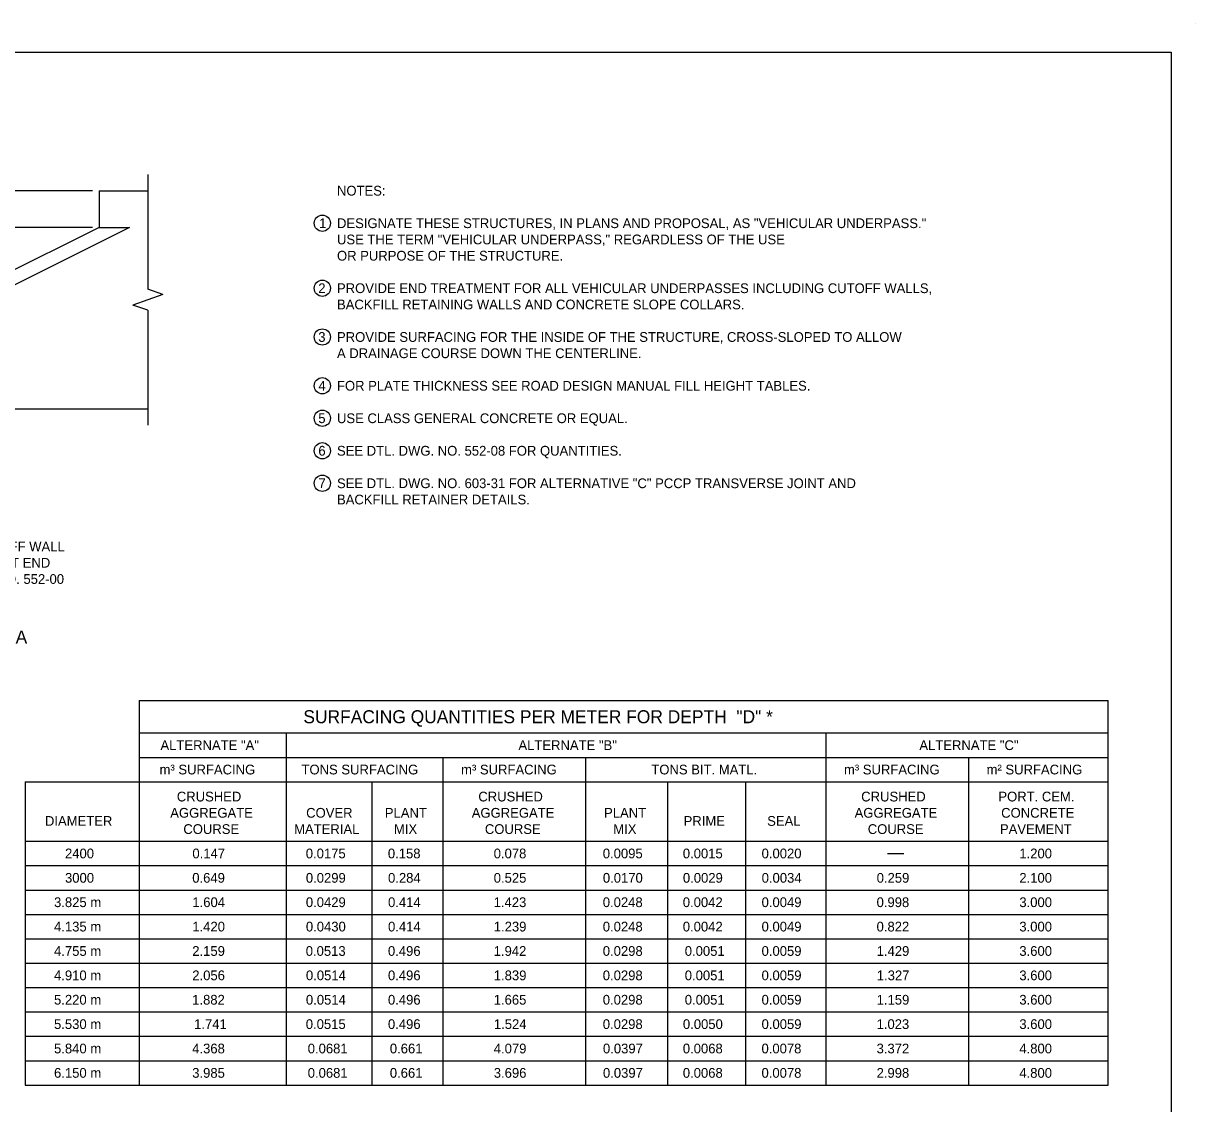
# Model space of a CAD drawing. Extents: x 49991.4 to 50021, y 49987.6 to 50011.4.
# Drawn here: x 50009.69 to 50016.9, y 49992.53 to 49999.18 of the extents above; entities that cross this region are included whole.
import ezdxf

# ---------------------------------------------------------------- set-up
doc = ezdxf.new("R2010")
doc.units = 0
for name, color, linetype in [('Level 1', 7, 'Continuous'), ('Level 2', 7, 'Continuous'), ('Level 3', 7, 'Continuous'), ('Level 6', 7, 'Continuous')]:
    doc.layers.add(name, color=color, linetype=linetype)

msp = doc.modelspace()

# ---------------------------------------------------------------- linework, layer by layer
at = {"layer": 'Level 1'}
for p, q in [((50016.9001, 49999.1756), (50016.9001, 49999.1756)), ((50010.1574, 49998.1464), (50010.1574, 49997.9206)), ((50010.1574, 49998.1464), (50010.4571, 49998.1464)), ((50010.1574, 49997.9206), (50008.3776, 49997.0307)), ((50010.3438, 49997.9206), (50008.4946, 49996.996)), ((50010.1574, 49997.9206), (50010.3438, 49997.9206)), ((50008.4946, 49996.8045), (50010.4571, 49996.8045))]:
    msp.add_line(p, q, dxfattribs=at)
msp.add_lwpolyline([(49999.3835, 49998.9992), (50016.7501, 49998.9992), (50016.7501, 49987.7988), (49999.3835, 49987.7988)], close=True, dxfattribs=at)
at = {"layer": 'Level 2'}
for p, q in [((50010.4028, 49995.0101), (50010.4028, 49992.6438)), ((50010.4028, 49995.0101), (50016.3623, 49995.0101)), ((50016.3623, 49992.6438), (50016.3623, 49995.0101)), ((50010.4028, 49994.8101), (50016.3623, 49994.8101)), ((50011.3081, 49994.8101), (50011.3081, 49992.6438)), ((50014.6266, 49994.8101), (50014.6266, 49992.6438)), ((50010.4028, 49994.6601), (50016.3623, 49994.6601)), ((50012.272, 49994.6601), (50012.272, 49992.6438)), ((50013.1491, 49994.6601), (50013.1491, 49992.6438)), ((50015.5037, 49994.6601), (50015.5037, 49992.6438)), ((50009.7028, 49994.5101), (50009.7028, 49992.6438)), ((50009.7028, 49994.5101), (50016.3623, 49994.5101)), ((50011.8348, 49994.5101), (50011.8348, 49992.6438)), ((50013.6524, 49994.5101), (50013.6524, 49992.6438)), ((50014.1334, 49994.5101), (50014.1334, 49992.6438)), ((50009.7028, 49994.1438), (50016.3623, 49994.1438)), ((50015.0067, 49994.0688), (50015.1058, 49994.0688)), ((50009.7028, 49993.9938), (50016.3623, 49993.9938)), ((50009.7028, 49993.8438), (50016.3623, 49993.8438)), ((50009.7028, 49993.6938), (50016.3623, 49993.6938)), ((50009.7028, 49993.5438), (50016.3623, 49993.5438)), ((50009.7028, 49993.3938), (50016.3623, 49993.3938)), ((50009.7028, 49993.2438), (50016.3623, 49993.2438)), ((50009.7028, 49993.0938), (50016.3623, 49993.0938)), ((50009.7028, 49992.9438), (50016.3623, 49992.9438)), ((50009.7028, 49992.7938), (50016.3623, 49992.7938)), ((50009.7028, 49992.6438), (50016.3623, 49992.6438))]:
    msp.add_line(p, q, dxfattribs=at)
for centre in [(50011.5303, 49997.9464), (50011.5303, 49997.5464), (50011.5303, 49997.2464), (50011.5303, 49996.9464), (50011.5303, 49996.7464), (50011.5303, 49996.5464), (50011.5303, 49996.3464)]:
    msp.add_circle(centre, 0.05, dxfattribs=at)
at = {"layer": 'Level 3'}
for p, q in [((50010.1174, 49998.1464), (50008.0477, 49998.1464)), ((50010.1174, 49997.9206), (50008.0477, 49997.9206))]:
    msp.add_line(p, q, dxfattribs=at)
at = {"layer": 'Level 6'}
for p, q in [((50010.4571, 49998.2464), (50010.4571, 49997.5402)), ((50010.5485, 49997.5078), (50010.4571, 49997.5402)), ((50010.4571, 49997.4754), (50010.3657, 49997.443)), ((50010.4571, 49997.4106), (50010.3657, 49997.443)), ((50010.5485, 49997.5078), (50010.4571, 49997.4754)), ((50010.4571, 49997.4106), (50010.4571, 49996.7045))]:
    msp.add_line(p, q, dxfattribs=at)

# ---------------------------------------------------------------- texts
at = {"layer": 'Level 2'}
for s, height, p in [('NOTES:', 0.06, (50011.6203, 49998.1164)), ('1', 0.06, (50011.5105, 49997.9164)), ('DESIGNATE THESE STRUCTURES, IN PLANS AND PROPOSAL, AS "VEHICULAR UNDERPASS."', 0.06, (50011.6203, 49997.9164)), ('USE THE TERM "VEHICULAR UNDERPASS," REGARDLESS OF THE USE', 0.06, (50011.6203, 49997.8164)), ('OR PURPOSE OF THE STRUCTURE.', 0.06, (50011.6203, 49997.7164)), ('2', 0.06, (50011.5051, 49997.5164)), ('PROVIDE END TREATMENT FOR ALL VEHICULAR UNDERPASSES INCLUDING CUTOFF WALLS,', 0.06, (50011.6203, 49997.5164)), ('BACKFILL RETAINING WALLS AND CONCRETE SLOPE COLLARS.', 0.06, (50011.6203, 49997.4164)), ('3', 0.06, (50011.5051, 49997.2164)), ('PROVIDE SURFACING FOR THE INSIDE OF THE STRUCTURE, CROSS-SLOPED TO ALLOW', 0.06, (50011.6203, 49997.2164)), ('A DRAINAGE COURSE DOWN THE CENTERLINE.', 0.06, (50011.6203, 49997.1164)), ('4', 0.06, (50011.5063, 49996.9164)), ('FOR PLATE THICKNESS SEE ROAD DESIGN MANUAL FILL HEIGHT TABLES.', 0.06, (50011.6203, 49996.9164)), ('5', 0.06, (50011.5054, 49996.7164)), ('USE CLASS GENERAL CONCRETE OR EQUAL.', 0.06, (50011.6203, 49996.7164)), ('6', 0.06, (50011.5058, 49996.5164)), ('SEE DTL. DWG. NO. 552-08 FOR QUANTITIES.', 0.06, (50011.6203, 49996.5164)), ('7', 0.06, (50011.5065, 49996.3164)), ('SEE DTL. DWG. NO. 603-31 FOR ALTERNATIVE "C" PCCP TRANSVERSE JOINT AND', 0.06, (50011.6203, 49996.3164)), ('BACKFILL RETAINER DETAILS.', 0.06, (50011.6203, 49996.2164)), ('CONCRETE CUTOFF WALL', 0.06, (50008.9074, 49995.9273)), ('INLET AND OUTLET END', 0.06, (50008.9074, 49995.8273)), ('SEE DTL. DWG. NO. 552-00', 0.06, (50008.9074, 49995.7273)), ('SECTION A-A', 0.08, (50009.0318, 49995.3602)), ('SURFACING QUANTITIES PER METER FOR DEPTH  "D" *', 0.08, (50011.4135, 49994.8701)), ('ALTERNATE "A"', 0.06, (50010.5348, 49994.7051)), ('ALTERNATE "B"', 0.06, (50012.7361, 49994.7051)), ('ALTERNATE "C"', 0.06, (50015.2017, 49994.7051)), ('m³ SURFACING', 0.06, (50010.5292, 49994.5551)), ('TONS SURFACING', 0.06, (50011.4021, 49994.5551)), ('m³ SURFACING', 0.06, (50012.3834, 49994.5551)), ('TONS BIT. MATL.', 0.06, (50013.5535, 49994.5551)), ('m³ SURFACING', 0.06, (50014.7379, 49994.5551)), ('m² SURFACING', 0.06, (50015.6151, 49994.5551)), ('CRUSHED', 0.06, (50010.6353, 49994.3888)), ('CRUSHED', 0.06, (50012.4895, 49994.3888)), ('CRUSHED', 0.06, (50014.844, 49994.3888)), ('PORT. CEM.', 0.06, (50015.6876, 49994.3888)), ('AGGREGATE', 0.06, (50010.5948, 49994.2888)), ('COVER', 0.06, (50011.4307, 49994.2888)), ('PLANT', 0.06, (50011.9144, 49994.2888)), ('AGGREGATE', 0.06, (50012.4489, 49994.2888)), ('PLANT', 0.06, (50013.2628, 49994.2888)), ('AGGREGATE', 0.06, (50014.8035, 49994.2888)), ('CONCRETE', 0.06, (50015.7047, 49994.2888)), ('DIAMETER', 0.06, (50009.8243, 49994.2388)), ('PRIME', 0.06, (50013.752, 49994.2388)), ('SEAL', 0.06, (50014.2658, 49994.2388)), ('COURSE', 0.06, (50010.6755, 49994.1888)), ('MATERIAL', 0.06, (50011.3568, 49994.1888)), ('MIX', 0.06, (50011.9708, 49994.1888)), ('COURSE', 0.06, (50012.5297, 49994.1888)), ('MIX', 0.06, (50013.3193, 49994.1888)), ('COURSE', 0.06, (50014.8843, 49994.1888)), ('PAVEMENT', 0.06, (50015.6971, 49994.1888)), ('2400', 0.06, (50009.9477, 49994.0388)), ('0.147', 0.06, (50010.7311, 49994.0388)), ('0.0175', 0.06, (50011.4284, 49994.0388)), ('0.158', 0.06, (50011.9332, 49994.0388)), ('0.078', 0.06, (50012.584, 49994.0388)), ('0.0095', 0.06, (50013.2548, 49994.0388)), ('0.0015', 0.06, (50013.747, 49994.0388)), ('0.0020', 0.06, (50014.2315, 49994.0388)), ('1.200', 0.06, (50015.8164, 49994.0388)), ('3000', 0.06, (50009.9477, 49993.8888)), ('0.649', 0.06, (50010.7303, 49993.8888)), ('0.0299', 0.06, (50011.4288, 49993.8888)), ('0.284', 0.06, (50011.9342, 49993.8888)), ('0.525', 0.06, (50012.5842, 49993.8888)), ('0.0170', 0.06, (50013.2554, 49993.8888)), ('0.0029', 0.06, (50013.7475, 49993.8888)), ('0.0034', 0.06, (50014.2319, 49993.8888)), ('0.259', 0.06, (50014.9391, 49993.8888)), ('2.100', 0.06, (50015.8164, 49993.8888)), ('3.825 m', 0.06, (50009.8802, 49993.7388)), ('1.604', 0.06, (50010.7309, 49993.7388)), ('0.0429', 0.06, (50011.4288, 49993.7388)), ('0.414', 0.06, (50011.9342, 49993.7388)), ('1.423', 0.06, (50012.5838, 49993.7388)), ('0.0248', 0.06, (50013.2548, 49993.7388)), ('0.0042', 0.06, (50013.7468, 49993.7388)), ('0.0049', 0.06, (50014.2314, 49993.7388)), ('0.998', 0.06, (50014.9386, 49993.7388)), ('3.000', 0.06, (50015.8164, 49993.7388)), ('4.135 m', 0.06, (50009.8802, 49993.5888)), ('1.420', 0.06, (50010.7306, 49993.5888)), ('0.0430', 0.06, (50011.429, 49993.5888)), ('0.414', 0.06, (50011.9342, 49993.5888)), ('1.239', 0.06, (50012.5845, 49993.5888)), ('0.0248', 0.06, (50013.2548, 49993.5888)), ('0.0042', 0.06, (50013.7468, 49993.5888)), ('0.0049', 0.06, (50014.2314, 49993.5888)), ('0.822', 0.06, (50014.9385, 49993.5888)), ('3.000', 0.06, (50015.8164, 49993.5888)), ('4.755 m', 0.06, (50009.8802, 49993.4388)), ('2.159', 0.06, (50010.7303, 49993.4388)), ('0.0513', 0.06, (50011.4281, 49993.4388)), ('0.496', 0.06, (50011.9337, 49993.4388)), ('1.942', 0.06, (50012.5839, 49993.4388)), ('0.0298', 0.06, (50013.2548, 49993.4388)), ('0.0051', 0.06, (50013.759, 49993.4388)), ('0.0059', 0.06, (50014.2314, 49993.4388)), ('1.429', 0.06, (50014.9391, 49993.4388)), ('3.600', 0.06, (50015.8164, 49993.4388)), ('4.910 m', 0.06, (50009.8802, 49993.2888)), ('2.056', 0.06, (50010.7304, 49993.2888)), ('0.0514', 0.06, (50011.4293, 49993.2888)), ('0.496', 0.06, (50011.9337, 49993.2888)), ('1.839', 0.06, (50012.5845, 49993.2888)), ('0.0298', 0.06, (50013.2548, 49993.2888)), ('0.0051', 0.06, (50013.759, 49993.2888)), ('0.0059', 0.06, (50014.2314, 49993.2888)), ('1.327', 0.06, (50014.9399, 49993.2888)), ('3.600', 0.06, (50015.8164, 49993.2888)), ('5.220 m', 0.06, (50009.8802, 49993.1388)), ('1.882', 0.06, (50010.7297, 49993.1388)), ('0.0514', 0.06, (50011.4293, 49993.1388)), ('0.496', 0.06, (50011.9337, 49993.1388)), ('1.665', 0.06, (50012.5842, 49993.1388)), ('0.0298', 0.06, (50013.2548, 49993.1388)), ('0.0051', 0.06, (50013.759, 49993.1388)), ('0.0059', 0.06, (50014.2314, 49993.1388)), ('1.159', 0.06, (50014.9391, 49993.1388)), ('3.600', 0.06, (50015.8164, 49993.1388)), ('5.530 m', 0.06, (50009.8802, 49992.9888)), ('1.741', 0.06, (50010.7418, 49992.9888)), ('0.0515', 0.06, (50011.4284, 49992.9888)), ('0.496', 0.06, (50011.9337, 49992.9888)), ('1.524', 0.06, (50012.5851, 49992.9888)), ('0.0298', 0.06, (50013.2548, 49992.9888)), ('0.0050', 0.06, (50013.7476, 49992.9888)), ('0.0059', 0.06, (50014.2314, 49992.9888)), ('1.023', 0.06, (50014.9385, 49992.9888)), ('3.600', 0.06, (50015.8164, 49992.9888)), ('5.840 m', 0.06, (50009.8802, 49992.8388)), ('4.368', 0.06, (50010.7299, 49992.8388)), ('0.0681', 0.06, (50011.4404, 49992.8388)), ('0.661', 0.06, (50011.9452, 49992.8388)), ('4.079', 0.06, (50012.5845, 49992.8388)), ('0.0397', 0.06, (50013.2559, 49992.8388)), ('0.0068', 0.06, (50013.747, 49992.8388)), ('0.0078', 0.06, (50014.2309, 49992.8388)), ('3.372', 0.06, (50014.9385, 49992.8388)), ('4.800', 0.06, (50015.8164, 49992.8388)), ('6.150 m', 0.06, (50009.8802, 49992.6888)), ('3.985', 0.06, (50010.73, 49992.6888)), ('0.0681', 0.06, (50011.4404, 49992.6888)), ('0.661', 0.06, (50011.9452, 49992.6888)), ('3.696', 0.06, (50012.5845, 49992.6888)), ('0.0397', 0.06, (50013.2559, 49992.6888)), ('0.0068', 0.06, (50013.747, 49992.6888)), ('0.0078', 0.06, (50014.2309, 49992.6888)), ('2.998', 0.06, (50014.9386, 49992.6888)), ('4.800', 0.06, (50015.8164, 49992.6888))]:
    msp.add_text(s, height=height, dxfattribs=at).set_placement(p)

doc.saveas('drawing.dxf')
